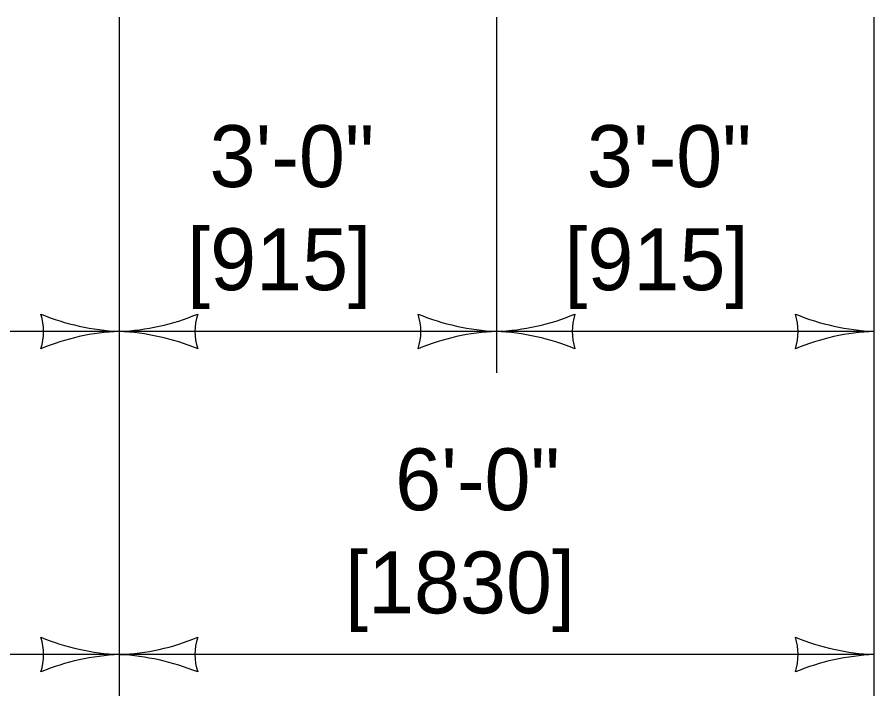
# Model space of a CAD drawing. Extents: x 49991.4 to 50021, y 49987.6 to 50011.4.
# Drawn here: x 50004.377 to 50005.208, y 49996.05 to 49996.708 of the extents above; entities that cross this region are included whole.
import ezdxf

# ---------------------------------------------------------------- set-up
doc = ezdxf.new("R2010")
doc.units = 0
doc.layers.add('Level 2', color=7, linetype='Continuous')
doc.layers.add('Level 3', color=7, linetype='Continuous')

msp = doc.modelspace()

# ---------------------------------------------------------------- linework, layer by layer
at = {"layer": 'Level 3'}
for p, q in [((50004.4764, 49996.70844), (50004.4764, 49996.05024)), ((50004.8424, 49996.70844), (50004.8424, 49996.36366)), ((50005.2084, 49996.70844), (50005.2084, 49996.05024)), ((50004.4764, 49996.40366), (50004.1104, 49996.40366)), ((50004.8424, 49996.40366), (50004.4764, 49996.40366)), ((50005.2084, 49996.40366), (50004.8424, 49996.40366)), ((50004.4764, 49996.09024), (50003.7444, 49996.09024)), ((50005.2084, 49996.09024), (50004.4764, 49996.09024))]:
    msp.add_line(p, q, dxfattribs=at)
for centre, radius, start, end in [((50004.34819, 49996.40366), 0.05477, 342.13882, 17.86118), ((50004.48789, 49996.63638), 0.233, 247.92284, 267.17269), ((50004.46724, 49996.6258), 0.22232, 272.36048, 292.54399), ((50004.60461, 49996.40366), 0.05477, 162.13882, 197.86118), ((50004.71419, 49996.40366), 0.05477, 342.13882, 17.86118), ((50004.85389, 49996.63638), 0.233, 247.92284, 267.17269), ((50004.83324, 49996.6258), 0.22232, 272.36048, 292.54399), ((50004.97061, 49996.40366), 0.05477, 162.13882, 197.86118), ((50005.08019, 49996.40366), 0.05477, 342.13882, 17.86118), ((50005.21989, 49996.63638), 0.233, 247.92284, 267.17269), ((50004.48556, 49996.18153), 0.22232, 92.36048, 112.54399), ((50004.46491, 49996.17095), 0.233, 67.92284, 87.17269), ((50004.85156, 49996.18153), 0.22232, 92.36048, 112.54399), ((50004.83091, 49996.17095), 0.233, 67.92284, 87.17269), ((50005.21756, 49996.18153), 0.22232, 92.36048, 112.54399), ((50004.34819, 49996.09024), 0.05477, 342.13882, 17.86118), ((50004.48789, 49996.32295), 0.233, 247.92284, 267.17269), ((50004.46724, 49996.31237), 0.22232, 272.36048, 292.54399), ((50004.60461, 49996.09024), 0.05477, 162.13882, 197.86118), ((50005.08019, 49996.09024), 0.05477, 342.13882, 17.86118), ((50005.21989, 49996.32295), 0.233, 247.92284, 267.17269), ((50004.48556, 49995.8681), 0.22232, 92.36048, 112.54399), ((50004.46491, 49995.85752), 0.233, 67.92284, 87.17269), ((50005.21756, 49995.8681), 0.22232, 92.36048, 112.54399)]:
    msp.add_arc(centre, radius, start, end, dxfattribs=at)

# ---------------------------------------------------------------- texts
at = {"layer": 'Level 2'}
for s, p in [('3\'-0"', (50004.56401, 49996.54366)), ('3\'-0"', (50004.93001, 49996.54366)), ('[915]', (50004.54226, 49996.44366)), ('[915]', (50004.90826, 49996.44366)), ('6\'-0"', (50004.74406, 49996.23024)), ('[1830]', (50004.69537, 49996.13024))]:
    msp.add_text(s, height=0.06, dxfattribs=at).set_placement(p)

doc.saveas('drawing.dxf')
